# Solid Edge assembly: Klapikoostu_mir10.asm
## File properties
Author: Türk
Template: Iso Assembly.asm
Last saved by: Türk
Revision: 3
Application: Solid Edge
Username: Türk
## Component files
Klapi vedru_mir2.par
Klapp.par
Klapipuks.par
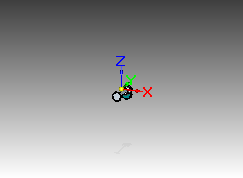
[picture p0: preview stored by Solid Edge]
